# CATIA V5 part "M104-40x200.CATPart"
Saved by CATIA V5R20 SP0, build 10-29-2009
Part number: M104-40x200
Source: Unknown
Bounding box of the stored display mesh (mm): x -19.994 to 19.994, y -19.994 to 19.994, z 0 to 200
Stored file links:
  C:\Users\Utente\Desktop\IO LAVORO\3D X SITO CF\X SITO\M104\M104-40x200.CATPart

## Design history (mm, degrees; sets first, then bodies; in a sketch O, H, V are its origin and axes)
Body1 (main body)
  Solid1 "PartBody": solid without history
